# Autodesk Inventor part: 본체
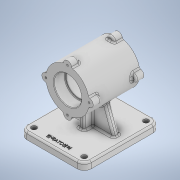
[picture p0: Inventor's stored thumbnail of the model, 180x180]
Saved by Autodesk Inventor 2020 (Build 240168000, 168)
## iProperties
Created: 2022-11
Part Number: 본체
Material: 일반
Document SubType Name: Modeling
Designer: Owner
Density: 1 g/cm^3
Appearance: 기본값
Mass: 450.145 g
Surface Area: 796.917 cm^2
Volume: 450.145 cm^3
Author: Owner
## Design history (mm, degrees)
sketch "스케치1"
  geometry: C1 r 7 at (0, 37); C2 r 7 at (37, 0); C3 r 7 at (0, -37); C4 r 7 at (-37, 0); A1 r 37 centre (0, 0) between (0, 37) and (37, 0); 9 further points
  constraints: 5 centre point, 4 point on circle, 2 horizontal alignment, 2 vertical alignment, 1 coincident
  dimensions: "d0" = 74 diameter of A1; "d1" = 14 diameter of C1; "d2" = 14 diameter of C2; "d3" = 14 diameter of C3; "d4" = 14 diameter of C4
extrude "돌출1" new body sketch "스케치1" stored distance "d5" = 87; taper "d6" = 0 deg
sketch "스케치2"
  geometry: A1 r 37 centre (0, 0) between (36.338, 6.969) and (6.969, 36.338) reference; 2 further points
  constraints: 1 coincident
hole "구멍1" sketch "스케치2" at (0, 0) diameter "d7" = 42; stored, may be unused: countersink angle "d11" = 90 deg, drill point angle "d13" = 0 deg; dims "d8" = 8, "d9" = 47, "d10" = 19, "d12" = 68
sketch "스케치3"
  geometry: A1 r 37 centre (0, 0) between (36.338, 6.969) and (6.969, 36.338) reference; 2 further points
  constraints: 1 coincident
hole "구멍2" sketch "스케치3" at (0, 0) diameter "d14" = 47; stored, may be unused: countersink angle "d18" = 90 deg, drill point angle "d20" = 0 deg; dims "d15" = 8, "d16" = 47, "d17" = 19, "d19" = 19
sketch "스케치4"
  geometry: 1 further point
node "작업 평면1"
sketch "스케치11"
  geometry: L1 (-37, -43.5)-(37, -43.5) reference; L2 (37, 43.5)-(-37, 43.5) reference; L3 (-55, -60)-(55, -60); L4 (55, -60)-(55, 70); L5 (55, 70)-(-55, 70); L6 (-55, 70)-(-55, -60); 2 further points
  constraints: 8 end point, 2 parallel, 1 horizontal, 1 midpoint, 1 perpendicular, 1 vertical alignment
  dimensions: "d49" = 130 distance of L3.end L4.end; "d50" = 70 distance from line of L5 point (0, 0); "d51" = 110 distance of L3.start L3.end
extrude "돌출3" join sketch "스케치11" distance "d52" = 12; taper "d53" = 0 deg
fillet "모깎기2" dims "d54" = 12
sketch "스케치12"
  geometry: 1 further point
sketch "스케치13"
  geometry: A1 r 12 centre (-43, -58) between (-55, -58) and (-43, -70) reference; 2 further points
  constraints: 1 coincident
hole "구멍6" sketch "스케치13" at (-43, -58) diameter "d55" = 9; stored, may be unused: countersink angle "d59" = 90 deg, drill point angle "d61" = 0 deg; dims "d56" = 8, "d57" = 47, "d58" = 19, "d60" = 19
sketch "스케치14"
  geometry: A1 r 12 centre (43, -58) between (43, -70) and (55, -58) reference; 2 further points
  constraints: 1 coincident
hole "구멍7" sketch "스케치14" at (43, -58) diameter "d62" = 9; stored, may be unused: countersink angle "d66" = 90 deg, drill point angle "d68" = 0 deg; dims "d63" = 8, "d64" = 47, "d65" = 19, "d67" = 19
sketch "스케치15"
  geometry: A1 r 12 centre (-43, 48) between (-43, 60) and (-55, 48) reference; 2 further points
  constraints: 1 coincident
hole "구멍8" sketch "스케치15" at (-43, 48) diameter "d69" = 9; stored, may be unused: countersink angle "d73" = 90 deg, drill point angle "d75" = 0 deg; dims "d70" = 8, "d71" = 47, "d72" = 19, "d74" = 19
sketch "스케치16"
  geometry: A1 r 12 centre (43, 48) between (55, 48) and (43, 60) reference; 2 further points
  constraints: 1 coincident
hole "구멍9" sketch "스케치16" at (43, 48) diameter "d76" = 9; stored, may be unused: countersink angle "d80" = 90 deg, drill point angle "d82" = 0 deg; dims "d77" = 8, "d78" = 47, "d79" = 19, "d81" = 19
sketch "스케치17"
  geometry: L1 (-43, -70)-(43, -70) reference; L2 (41, -70)-(25.336, -26.964); L3 (55, -82)-(55, -70) reference; L4 (-41, -70)-(-25.336, -26.964); L5 (-55, -70)-(-55, -82) reference; A1 r 37 centre (0, 0) between (25.336, -26.964) and (-25.336, -26.964) reference; 1 further point
  constraints: 4 end point, 2 point on circle, 2 point on line
  dimensions: "d83" = 14 distance from line of L3 L2.start; "d84" = 110 deg angle of L1 L2; "d85" = 14 distance from line of L5 L4.start; "d86" = 110 deg angle of L1 L4
extrude "돌출4" join sketch "스케치17" stored distance "d87" = 10; taper "d88" = 0 deg
sketch "스케치18"
  geometry: L1 (-70, -48)-(-70, 58) reference; L2 (-70, 5)-(-70, -5) reference; L3 (-26.964, 5)-(-70, 5) reference; L4 (-26.964, -5)-(-26.964, 5) reference; L5 (-70, -5)-(-26.964, -5) reference; L6 (-70, 20)-(-47.493, 20); 1 further point
  constraints: 2 end point, 1 horizontal, 1 point on line
  dimensions: "d89" = 20 vertical distance of point (0, 0) L6.start
feature "리브1" sketch "스케치18" dims "d90" = 1, "d91" = 10, "d92" = 0, "d93" = 0, "d94" = 1, "d95" = 1
sketch "스케치19"
  geometry: C1 r 23.5 at (0, 0) reference; C2 r 7 at (0, 37); C3 r 7 at (37, 0); C4 r 7 at (-37, 0); C5 r 7 at (0, -37); A1 r 37 centre (0, 0) between (-5, -36.661) and (5, -36.661) reference; A2 r 37 centre (0, 0) between (0, 37) and (37, 0) reference; A3 r 37 centre (0, 0) between (-5, -36.661) and (5, -36.661) reference; 9 further points
  constraints: 4 centre point, 4 point on circle, 2 horizontal alignment, 1 vertical alignment
  dimensions: "d96" = 14 diameter of C2; "d97" = 14 diameter of C3; "d98" = 14 diameter of C4; "d100" = 14 diameter of C5
extrude "돌출5" join sketch "스케치19" distance "d101" = 14; taper "d102" = 0 deg
sketch "스케치20"
  geometry: A1 r 7 centre (0, 37) between (6.969, 36.338) and (-6.969, 36.338) reference; 2 further points
  constraints: 1 coincident
hole "구멍10" sketch "스케치20" at (0, 37) diameter "d103" = 3.242; stored, may be unused: countersink angle "d107" = 90 deg, drill point angle "d109" = 118 deg; dims "d104" = 8, "d105" = 47, "d106" = 19, "d108" = 10
sketch "스케치21"
  geometry: A1 r 7 centre (0, 37) between (6.969, 36.338) and (-6.969, 36.338) reference; 2 further points
  constraints: 1 coincident
hole "구멍11" sketch "스케치21" at (0, 37) diameter "d113" = 3.242; stored, may be unused: countersink angle "d117" = 90 deg, drill point angle "d119" = 118 deg; dims "d114" = 8, "d115" = 47, "d116" = 19, "d118" = 10
fillet "모깎기3" dims "d123" = 3
fillet "모깎기4" dims "d124" = 3
fillet "모깎기5" dims "d125" = 3
fillet "모깎기6" dims "d126" = 3
fillet "모깎기7" dims "d127" = 3
fillet "모깎기8" dims "d128" = 3
fillet "모깎기9" dims "d129" = 3
fillet "모깎기10" dims "d130" = 3
fillet "모깎기11" dims "d131" = 3
fillet "모깎기12" dims "d132" = 3
fillet "모깎기13" dims "d133" = 3
fillet "모깎기14" dims "d134" = 3
fillet "모깎기15" dims "d135" = 3
fillet "모깎기16" dims "d136" = 3
fillet "모깎기17" dims "d137" = 3
fillet "모깎기18" dims "d138" = 3
fillet "모깎기19" dims "d139" = 3
fillet "모깎기20" dims "d140" = 3
sketch "스케치22"
  geometry: L1 (-43, -70)-(43, -70) reference; 3 further points
  constraints: 1 midpoint, 1 vertical alignment, 1 other
  dimensions: "d141" = 12 distance from line of L1 point (0, -58)
feature "엠보싱1" sketch "스케치22" dims "d14" = 47, "d142" = 0.5, "d143" = 0
chamfer "모따기1" distance "d144" = 1; stored, may be unused: second distance "d145" = 2, angle "d146" = 45 deg
fillet "모깎기21" dims "d147" = 1
node "솔리드1"
mirror "미러1"
mirror "미러2"
pattern_circular "원형 패턴1" dims angle "d111" = 360 deg
pattern_circular "원형 패턴2" dims angle "d121" = 360 deg
node "투영된 루프4"
node "투영된 루프5"
node "투영된 루프6"
feature "A9D066F2-1C7D-4E18-AEED-F7BC21143FA4" dims "d7" = 42, "d8" = 8, "d9" = 47, "d10" = 19, "d11" = 90 deg, "d12" = 68, "d13" = 0
other parameters: "d21" = -82
